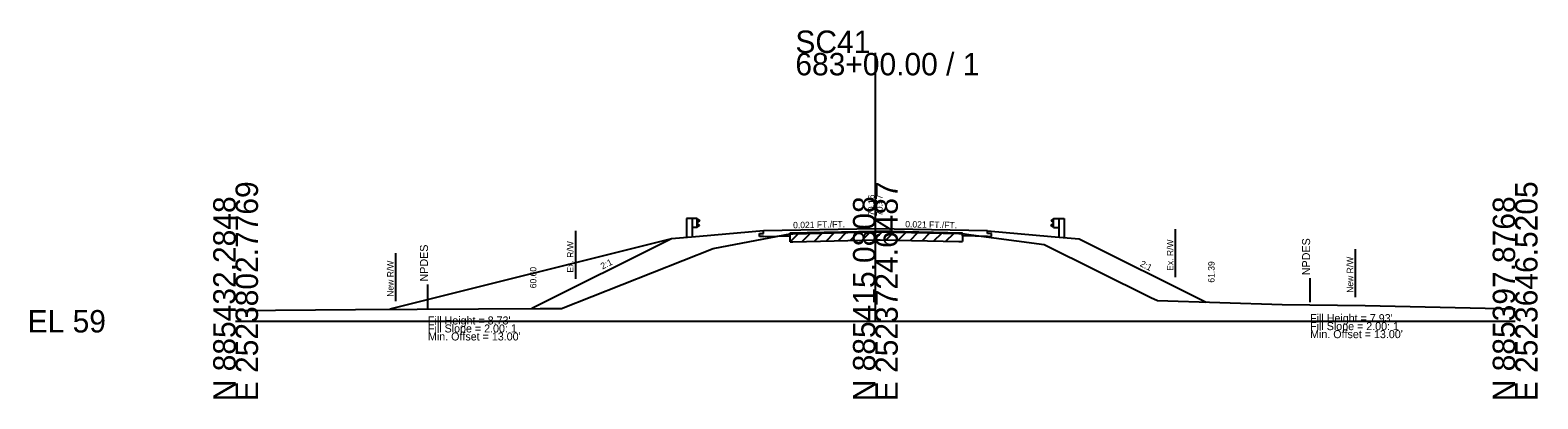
# Model space of a CAD drawing. Extents: x -26 to 183, y -10 to 24021.
# Drawn here: x -25.7 to 162.8, y 13490.3 to 13536.4 of the extents above; entities that cross this region are included whole.
import ezdxf

# ---------------------------------------------------------------- set-up
doc = ezdxf.new("R2010")
doc.units = 0
for name, color, linetype in [('RD_GPK_XS_Cell', 7, 'Continuous'), ('RD_XS_Base', 7, 'Continuous'), ('RD_XS_Buildup', 7, 'Continuous'), ('RD_XS_EarthShd', 7, 'Continuous'), ('RD_XS_ExGround', 7, 'Continuous'), ('RD_XS_ExPaveRet', 7, 'Continuous'), ('RD_XS_ExRW', 7, 'Continuous'), ('RD_XS_GR', 7, 'Continuous'), ('RD_XS_NewRW', 7, 'Continuous'), ('RD_XS_NPDES', 7, 'Continuous'), ('RD_XS_Pave', 7, 'Continuous'), ('RD_XS_TieSlope', 7, 'Continuous'), ('RD_XS_TX_Elev_EX', 7, 'Continuous'), ('RD_XS_TX_Elev_PR', 7, 'Continuous'), ('RD_XS_TX_Slope', 7, 'Continuous'), ('RD_XS_TX_Warning', 7, 'Continuous')]:
    doc.layers.add(name, color=color, linetype=linetype)

msp = doc.modelspace()

# ---------------------------------------------------------------- linework, layer by layer
at = {"layer": 'RD_GPK_XS_Cell'}
for p, q in [((80, 13500), (80, 13533.53)), ((0, 13500), (80, 13500)), ((80, 13500), (160, 13500))]:
    msp.add_line(p, q, dxfattribs=at)
at = {"layer": 'RD_XS_Base'}
for p, q in [((66, 13510.6), (69.33, 13510.67)), ((69.33, 13510.67), (69.33, 13510.91)), ((90.9, 13510.66), (90.9, 13510.96)), ((94, 13510.6), (90.9, 13510.66))]:
    msp.add_line(p, q, dxfattribs=at)
at = {"layer": 'RD_XS_Buildup'}
for p, q in [((69.33, 13511.03), (80, 13511.25)), ((69.33, 13510.91), (69.33, 13511.03)), ((90.9, 13511.02), (80, 13511.25)), ((90.9, 13510.96), (90.9, 13511.02))]:
    msp.add_line(p, q, dxfattribs=at)
at = {"layer": 'RD_XS_EarthShd'}
for p, q in [((58, 13510.61), (54.5, 13510.32)), ((66, 13511.28), (58, 13510.61)), ((94, 13511.28), (102, 13510.61)), ((102, 13510.61), (105.5, 13510.32))]:
    msp.add_line(p, q, dxfattribs=at)
at = {"layer": 'RD_XS_ExGround'}
for p, q in [((60.8, 13509.3), (69.33, 13510.91)), ((69.33, 13510.91), (69.67, 13510.92)), ((69.67, 13510.92), (80, 13511.16)), ((80, 13511.16), (80.58, 13511.18)), ((80.58, 13511.18), (90.43, 13510.97)), ((90.43, 13510.97), (90.9, 13510.96)), ((90.9, 13510.96), (91.37, 13510.9)), ((91.37, 13510.9), (101.11, 13509.59)), ((40.77, 13501.61), (59.7, 13509.09)), ((59.7, 13509.09), (60.8, 13509.3)), ((101.11, 13509.59), (114.44, 13502.97)), ((114.44, 13502.97), (115.29, 13502.59)), ((0, 13501.34), (14.99, 13501.49)), ((14.99, 13501.49), (38.08, 13501.6)), ((38.08, 13501.6), (39.89, 13501.6)), ((39.89, 13501.6), (40.77, 13501.61)), ((115.29, 13502.59), (130.88, 13502.08)), ((130.88, 13502.08), (141.25, 13501.99)), ((141.25, 13501.99), (160, 13501.54))]:
    msp.add_line(p, q, dxfattribs=at)
at = {"layer": 'RD_XS_ExPaveRet'}
for p, q in [((69.33, 13509.91), (70.36, 13510.93)), ((69.33, 13509.91), (69.33, 13510.91)), ((70.83, 13509.95), (71.86, 13510.97)), ((72.33, 13509.98), (73.36, 13511.01)), ((73.83, 13510.02), (74.86, 13511.04)), ((75.33, 13510.05), (76.36, 13511.08)), ((76.83, 13510.09), (77.86, 13511.11)), ((78.33, 13510.12), (79.36, 13511.15)), ((79.83, 13510.16), (80.84, 13511.17)), ((81.33, 13510.16), (82.31, 13511.14)), ((82.83, 13510.13), (83.81, 13511.11)), ((84.33, 13510.1), (85.31, 13511.08)), ((85.83, 13510.07), (86.81, 13511.05)), ((87.33, 13510.03), (88.31, 13511.01)), ((88.83, 13510), (89.81, 13510.98)), ((90.9, 13510.96), (90.9, 13509.96)), ((69.33, 13509.91), (69.67, 13509.92)), ((69.67, 13509.92), (80, 13510.16)), ((80, 13510.16), (80.58, 13510.18)), ((80.58, 13510.18), (90.43, 13509.97)), ((90.43, 13509.97), (90.9, 13509.96))]:
    msp.add_line(p, q, dxfattribs=at)
at = {"layer": 'RD_XS_ExRW'}
for p, q in [((42.5, 13511.3), (42.5, 13505.3)), ((117.5, 13511.51), (117.5, 13505.51))]:
    msp.add_line(p, q, dxfattribs=at)
at = {"layer": 'RD_XS_GR'}
for p, q in [((56.4, 13512.86), (56.4, 13510.48)), ((57.07, 13512.86), (56.4, 13512.86)), ((57.07, 13512.86), (57.07, 13510.53)), ((57.73, 13512.86), (57.07, 13512.86)), ((57.73, 13511.7), (57.73, 13512.86)), ((57.73, 13512.79), (58, 13512.59)), ((58, 13512.54), (57.73, 13512.34)), ((58, 13512.02), (57.73, 13512.22)), ((58, 13512.59), (58, 13512.54)), ((102.27, 13512.79), (102, 13512.59)), ((102, 13512.59), (102, 13512.54)), ((102, 13512.54), (102.27, 13512.34)), ((102, 13512.02), (102.27, 13512.22)), ((102.27, 13511.7), (102.27, 13512.86)), ((102.27, 13512.86), (102.93, 13512.86)), ((102.93, 13512.86), (102.93, 13510.53)), ((102.93, 13512.86), (103.6, 13512.86)), ((103.6, 13512.86), (103.6, 13510.48)), ((57.73, 13511.7), (57.06, 13511.7)), ((57.73, 13511.77), (58, 13511.97)), ((58, 13511.97), (58, 13512.02)), ((102, 13511.97), (102, 13512.02)), ((102.27, 13511.77), (102, 13511.97)), ((102.27, 13511.7), (102.94, 13511.7))]:
    msp.add_line(p, q, dxfattribs=at)
at = {"layer": 'RD_XS_NewRW'}
for p, q in [((20, 13508.52), (20, 13502.52)), ((140, 13509), (140, 13503))]:
    msp.add_line(p, q, dxfattribs=at)
at = {"layer": 'RD_XS_NPDES'}
for p, q in [((24.05, 13501.6), (24.05, 13504.6)), ((134.36, 13502.39), (134.36, 13505.39))]:
    msp.add_line(p, q, dxfattribs=at)
at = {"layer": 'RD_XS_Pave'}
for p, q in [((54.5, 13510.32), (19.28, 13501.51)), ((65.5, 13510.95), (66, 13510.96)), ((65.5, 13510.59), (65.5, 13510.95)), ((66, 13510.6), (65.5, 13510.59)), ((80, 13511.57), (66, 13511.28)), ((66, 13510.96), (66, 13511.28)), ((94, 13511.28), (80, 13511.57)), ((94, 13510.96), (94, 13511.28)), ((94.5, 13510.95), (94, 13510.96)), ((94, 13510.6), (94.5, 13510.59)), ((94.5, 13510.59), (94.5, 13510.95))]:
    msp.add_line(p, q, dxfattribs=at)
at = {"layer": 'RD_XS_TieSlope'}
for p, q in [((54.5, 13510.32), (37.05, 13501.6)), ((105.5, 13510.32), (121.36, 13502.39))]:
    msp.add_line(p, q, dxfattribs=at)

# ---------------------------------------------------------------- texts
at = {"layer": 'RD_GPK_XS_Cell'}
for s, p in [('SC41', (70, 13533.53)), ('683+00.00 / 1', (70, 13530.73)), ('EL 59', (-26, 13498.6))]:
    msp.add_text(s, height=2.8, dxfattribs=at).set_placement(p)
for s, p in [('E 2523802.7769', (2.8, 13490)), ('E 2523724.6487', (82.8, 13490)), ('E 2523646.5205', (162.8, 13490)), ('N 885432.2848', (0, 13490)), ('N 885415.0808', (80, 13490)), ('N 885397.8768', (160, 13490))]:
    msp.add_text(s, height=2.8, rotation=90, dxfattribs=at).set_placement(p)
at = {"layer": 'RD_XS_ExRW'}
for p in [(42.25, 13506.08), (117.25, 13506.3)]:
    msp.add_text('Ex. R/W ', height=0.8, rotation=90, dxfattribs=at).set_placement(p)
at = {"layer": 'RD_XS_NewRW'}
for p in [(19.75, 13503.06), (139.75, 13503.55)]:
    msp.add_text('New R/W ', height=0.8, rotation=90, dxfattribs=at).set_placement(p)
at = {"layer": 'RD_XS_TX_Elev_EX'}
msp.add_text('70.16', height=0.8, rotation=90, dxfattribs=at).set_placement((79.9, 13513.16))
at = {"layer": 'RD_XS_TX_Elev_PR'}
for s, p in [('70.57', (80.9, 13513.16)), ('60.60', (37.61, 13504.12)), ('61.39', (122.41, 13504.82))]:
    msp.add_text(s, height=0.8, rotation=90, dxfattribs=at).set_placement(p)
at = {"layer": 'RD_XS_TX_Slope'}
for s, rotation, p in [('0.021 FT./FT.', 1.1916, (69.72, 13511.61)), ('0.021 FT./FT.', 358.8084, (83.73, 13511.74)), ('2:1', 26.5651, (45.88, 13506.46)), ('2:1', 333.4349, (113.02, 13506.93))]:
    msp.add_text(s, height=0.8, rotation=rotation, dxfattribs=at).set_placement(p)
at = {"layer": 'RD_XS_TX_Warning'}
for p in [(134.36, 13505.39), (24.05, 13504.6)]:
    msp.add_text(' NPDES', height=1, rotation=90, dxfattribs=at).set_placement(p)
for s, p in [("Fill Height = 7.93' ", (134.36, 13499.89)), ("Fill Height = 8.73' ", (24.05, 13499.6)), ('Fill Slope = 2.00: 1', (24.05, 13498.6)), ('Fill Slope = 2.00: 1', (134.36, 13498.89)), ("Min. Offset = 13.00' ", (134.36, 13497.89)), ("Min. Offset = 13.00' ", (24.05, 13497.6))]:
    msp.add_text(s, height=1, dxfattribs=at).set_placement(p)

doc.saveas('drawing.dxf')
